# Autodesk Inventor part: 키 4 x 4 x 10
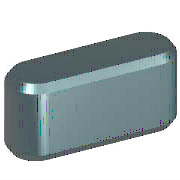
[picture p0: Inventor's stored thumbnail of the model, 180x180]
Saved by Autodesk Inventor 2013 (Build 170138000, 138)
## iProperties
IsCustomPart: 1
Created: 2012-02
Part Number: 키 4 x 4 x 10
Material: 강철, 연강
Description: 키 및 해당 키홈
Document SubType Name: Modeling
Standard: KS B 1311
Designer: mduedu
Standards Organization: KS
Language: ko-KR
Size Designation: 4 x 4 x 10
Categories: <MemberInstance><Categories><Category DisplayName="샤프트 부품" InternalName="7f7aeb1f-a693-4053-b835-cee3144e0d98" Mnemonic="SHFT"><Category DisplayName="키" Interna
Density: 1 g/cm^3
Author: mduedu
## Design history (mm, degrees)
workplane "Work Plane1"
workplane "Work Plane2"
sketch "스케치1"
  geometry: L1 (2, 2)-(8, 2); L2 (8, -2)-(2, -2); L3 (0, 9.4)-(0, -7.4) reference; L4 (-5, 0)-(30, 0) reference; L5 (10, 0)-(10, 7); A1 r 2 centre (2, 0) between (2, 2) and (2, -2); A2 r 2 centre (8, 0) between (8, -2) and (8, 2)
  constraints: 6 end point, 5 point on circle, 4 tangent, 3 point on line, 2 centre point, 1 horizontal, 1 parallel, 1 perpendicular
  dimensions: "d0" = 2 radius of A1 (= 0.5 x PB); "d13" = 2 radius of A2 (= 0.5 x PB); "d14" = 10 distance between parallel lines of L5 L3 (= NLG)
extrude "본체1" new body sketch "스케치1" taper "d3" = 0 deg; stored distance "d4" = 10
workplane "Work Plane3"
body "Solid1"
chamfer "모따기1" distance "d8" = 0.25 (= PHH); stored, may be unused: second distance "d9" = 0.25 (= PHH), angle "d15" = 45 deg
other parameters: "d1" = -2.5 (= -PNT), "d2" = 1.5 (= PH - PNT), "NLG" = 10 [user parameter; used in 3 equation terms], "PB" = 4 [user parameter; used in 2 equation terms], "PNT" = 2.5 [user parameter; used in 2 equation terms], "PH" = 4 [user parameter; used in 1 equation term], "PHH" = 0.25 [user parameter; used in 2 equation terms], "d10" = 0, "d16" = 0, "d17" = 0, "d18" = 0, "WDMAX" = 12 [user parameter], "RR" = 0.08 [user parameter], "PUEB" = 1.8 [user parameter]
